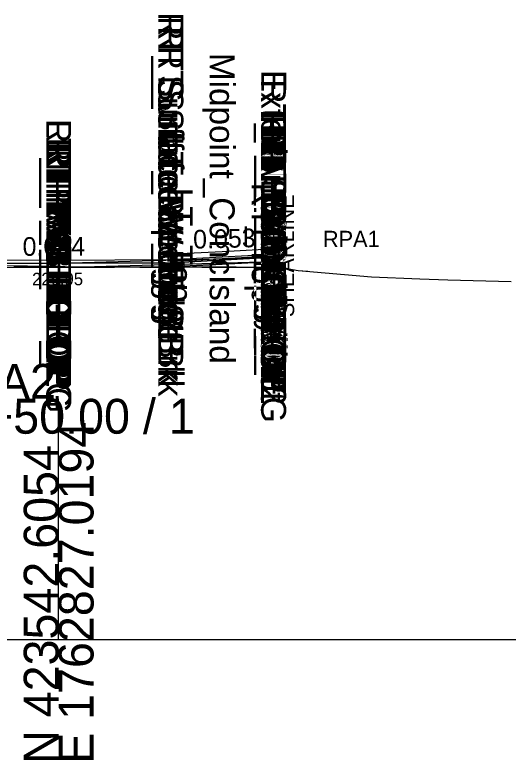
# Model space of a CAD drawing. Extents: x -26 to 3240, y -10 to 12522.
# Drawn here: x 96.5 to 136.1, y 1490.3 to 1550.2 of the extents above; entities that cross this region are included whole.
import ezdxf

# ---------------------------------------------------------------- set-up
doc = ezdxf.new("R2010")
doc.units = 0
for name, color, linetype in [('Exist CMT Pavement', 7, 'Continuous'), ('Exist Cross Section Cell', 7, 'Continuous'), ('Exist XS Center Line Elevation Label', 7, 'Continuous'), ('Exist XS Ground Line', 7, 'Continuous'), ('Prop CMT Concrete Structures', 7, 'Continuous'), ('Prop CMT DNC', 7, 'Continuous'), ('Prop CMT Pvmt Course 1', 7, 'Continuous'), ('Prop CMT Pvmt Course 1 Wedge', 7, 'Continuous'), ('Prop CMT Pvmt Course 2', 7, 'Continuous'), ('Prop CMT Pvmt Course 2 Wedge', 7, 'Continuous'), ('Prop CMT Pvmt Course 3', 7, 'Continuous'), ('Prop CMT Pvmt Course 3 Wedge', 7, 'Continuous'), ('Prop CMT Pvmt Surface', 7, 'Continuous'), ('Prop CMT Pvmt Wedge Surface 1', 7, 'Continuous'), ('Prop CMT Pvmt Wedge Surface 2', 7, 'Continuous'), ('Prop CMT Pvmt Wedge Surface 3', 7, 'Continuous'), ('Prop CMT Shear Line', 7, 'Continuous'), ('Prop CMT Shear Line Text', 7, 'Continuous'), ('Prop CMT Subgrade Earthwork', 7, 'Continuous'), ('Prop XS SE Text', 7, 'Continuous'), ('Scratch_Level_0', 7, 'Continuous')]:
    doc.layers.add(name, color=color, linetype=linetype)

msp = doc.modelspace()

# ---------------------------------------------------------------- linework, layer by layer
at = {"layer": 'Exist CMT Pavement'}
for points in [[(100, 1529.946), (90, 1530.058)], [(100, 1529.946), (90, 1530.058)], [(100, 1529.946), (117.248, 1529.875)], [(100, 1529.946), (117.248, 1529.875)]]:
    msp.add_lwpolyline(points, dxfattribs=at)
at = {"layer": 'Exist Cross Section Cell'}
for p, q in [((100, 1500), (100, 1519.323)), ((0, 1500), (100, 1500)), ((100, 1500), (200, 1500))]:
    msp.add_line(p, q, dxfattribs=at)
at = {"layer": 'Exist XS Ground Line'}
for points in [[(96.393, 1529.982), (96.557, 1529.98), (98.234, 1529.964), (99.198, 1529.955), (100.154, 1529.944), (100.52, 1529.941), (101.642, 1529.925), (102.088, 1529.921), (102.841, 1529.919), (104.97, 1529.914), (106.504, 1529.907), (107.848, 1529.902), (109.73, 1529.911), (110.741, 1529.917), (111.464, 1529.918), (113.742, 1529.916), (114.254, 1529.914), (116.398, 1529.902), (116.439, 1529.901), (116.494, 1529.901), (117.973, 1529.85), (118.184, 1529.825), (119.216, 1529.643), (125.115, 1529.122), (128.99, 1528.958), (131.239, 1528.886), (136.307, 1528.741)], [(96.393, 1529.982), (96.557, 1529.98), (98.234, 1529.964), (99.198, 1529.955), (100.154, 1529.944), (100.52, 1529.941), (101.642, 1529.925), (102.088, 1529.921), (102.841, 1529.919), (104.97, 1529.914), (106.504, 1529.907), (107.848, 1529.902), (109.73, 1529.911), (110.741, 1529.917), (111.464, 1529.918), (113.742, 1529.916), (114.254, 1529.914), (116.398, 1529.902), (116.439, 1529.901), (116.494, 1529.901), (117.973, 1529.85), (118.184, 1529.825), (119.216, 1529.643), (125.115, 1529.122), (128.99, 1528.958), (131.239, 1528.886), (136.306, 1528.741)], [(96.393, 1529.982), (96.557, 1529.98), (98.234, 1529.964), (99.198, 1529.955), (100.154, 1529.944), (100.52, 1529.941), (101.642, 1529.925), (102.088, 1529.921), (102.841, 1529.919), (104.97, 1529.914), (106.504, 1529.907), (107.848, 1529.902), (109.73, 1529.911), (110.741, 1529.917), (111.464, 1529.918), (113.742, 1529.916), (114.254, 1529.914), (116.398, 1529.902), (116.439, 1529.901), (116.494, 1529.901), (117.973, 1529.85), (118.184, 1529.825), (119.216, 1529.643), (120, 1529.574)]]:
    msp.add_lwpolyline(points, dxfattribs=at)
at = {"layer": 'Prop CMT Concrete Structures'}
for points in [[(117.248, 1531.11), (116.498, 1531.32), (113.124, 1531.14), (109.75, 1530.96), (109, 1530.67)], [(117.248, 1531.11), (116.498, 1531.32), (113.124, 1531.14), (109.75, 1530.96), (109, 1530.67)], [(117.248, 1530.818), (117.248, 1531.11)], [(117.248, 1530.818), (117.248, 1531.11)], [(109, 1530.377), (117.248, 1530.818)], [(109, 1530.377), (117.248, 1530.818)], [(109, 1530.67), (109, 1530.377)], [(109, 1530.67), (109, 1530.377)]]:
    msp.add_lwpolyline(points, dxfattribs=at)
at = {"layer": 'Prop CMT DNC'}
msp.add_lwpolyline([(117.248, 1529.777), (117.248, 1531.277)], dxfattribs=at)
msp.add_lwpolyline([(117.248, 1529.777), (117.248, 1531.277)], dxfattribs=at)
at = {"layer": 'Prop CMT Pvmt Course 1'}
for points in [[(100, 1530.463), (79.22, 1530.371)], [(100, 1530.463), (109, 1530.503), (117.248, 1530.943)], [(100, 1530.463), (109, 1530.503), (117.248, 1530.943)], [(117.248, 1530.693), (109, 1530.253), (100, 1530.213)], [(117.248, 1530.693), (109, 1530.253), (100, 1530.213)], [(100, 1530.213), (100, 1530.463)], [(100, 1530.213), (100, 1530.463)], [(100, 1530.213), (100, 1530.463)], [(117.248, 1530.943), (117.248, 1530.693), (117.248, 1530.693), (117.248, 1530.693)], [(117.248, 1530.943), (117.248, 1530.693), (117.248, 1530.693), (117.248, 1530.693)], [(90, 1530.169), (100, 1530.213)], [(100, 1530.213), (100, 1530.213), (100, 1530.213)], [(100, 1530.213), (100, 1530.213), (100, 1530.213)], [(100, 1530.213), (100, 1530.213), (100, 1530.213)]]:
    msp.add_lwpolyline(points, dxfattribs=at)
at = {"layer": 'Prop CMT Pvmt Course 1 Wedge'}
for points in [[(100, 1530.213), (117.248, 1530.693)], [(100, 1530.213), (117.248, 1530.693)], [(117.248, 1530.693), (109, 1530.253)], [(117.248, 1530.693), (109, 1530.253)], [(100, 1530.213), (90, 1530.169)], [(100, 1530.213), (90, 1530.169)], [(109, 1530.253), (100, 1530.213)], [(109, 1530.253), (100, 1530.213)]]:
    msp.add_lwpolyline(points, dxfattribs=at)
at = {"layer": 'Prop CMT Pvmt Course 2'}
for points in [[(117.248, 1530.36), (117.248, 1530.36), (117.248, 1530.693), (117.248, 1530.693)], [(117.248, 1530.693), (117.248, 1530.36)], [(117.248, 1530.36), (117.248, 1530.36), (117.248, 1530.693), (117.248, 1530.693)], [(117.248, 1530.693), (117.248, 1530.36)]]:
    msp.add_lwpolyline(points, dxfattribs=at)
at = {"layer": 'Prop CMT Pvmt Course 2 Wedge'}
for points in [[(100, 1530.213), (117.248, 1530.693)], [(100, 1530.213), (117.248, 1530.693)], [(117.248, 1530.693), (109, 1530.253)], [(117.248, 1530.693), (109, 1530.253)], [(100, 1530.213), (90, 1530.169)], [(100, 1530.213), (90, 1530.169)], [(109, 1530.253), (100, 1530.213)], [(109, 1530.253), (100, 1530.213)]]:
    msp.add_lwpolyline(points, dxfattribs=at)
at = {"layer": 'Prop CMT Pvmt Course 3'}
for points in [[(117.248, 1530.36), (117.248, 1530.36), (117.248, 1529.777), (117.248, 1529.777)], [(117.248, 1529.777), (117.248, 1530.36)], [(117.248, 1530.36), (117.248, 1530.36), (117.248, 1529.777), (117.248, 1529.777)], [(117.248, 1529.777), (117.248, 1530.36)]]:
    msp.add_lwpolyline(points, dxfattribs=at)
at = {"layer": 'Prop CMT Pvmt Course 3 Wedge'}
for points in [[(100, 1529.88), (90, 1529.836)], [(100, 1529.88), (90, 1529.836)], [(100, 1529.88), (117.248, 1530.36)], [(100, 1529.88), (117.248, 1530.36)], [(109, 1529.919), (100, 1529.88)], [(109, 1529.919), (100, 1529.88)], [(117.248, 1530.36), (109, 1529.919)], [(117.248, 1530.36), (109, 1529.919)]]:
    msp.add_lwpolyline(points, dxfattribs=at)
at = {"layer": 'Prop CMT Pvmt Surface'}
for points in [[(100, 1530.463), (79.22, 1530.371)], [(100, 1530.463), (109, 1530.503), (117.248, 1530.943)], [(100, 1530.463), (109, 1530.503), (117.248, 1530.943)]]:
    msp.add_lwpolyline(points, dxfattribs=at)
at = {"layer": 'Prop CMT Pvmt Wedge Surface 1'}
for points in [[(100, 1530.213), (109, 1530.253), (117.248, 1530.693)], [(100, 1530.213), (109, 1530.253), (117.248, 1530.693)], [(117.248, 1530.693), (117.248, 1530.943)], [(117.248, 1530.693), (117.248, 1530.943)], [(117.248, 1530.693), (117.248, 1530.693), (117.248, 1530.693)], [(117.248, 1530.693), (117.248, 1530.693), (117.248, 1530.693)], [(100, 1530.213), (90, 1530.169)]]:
    msp.add_lwpolyline(points, dxfattribs=at)
at = {"layer": 'Prop CMT Pvmt Wedge Surface 2'}
for points in [[(100, 1530.213), (109, 1530.253), (117.248, 1530.693)], [(100, 1530.213), (109, 1530.253), (117.248, 1530.693)], [(117.248, 1530.693), (117.248, 1530.943)], [(117.248, 1530.693), (117.248, 1530.943)], [(100, 1530.213), (79.22, 1530.121)]]:
    msp.add_lwpolyline(points, dxfattribs=at)
at = {"layer": 'Prop CMT Pvmt Wedge Surface 3'}
for points in [[(117.248, 1530.36), (117.248, 1530.943)], [(117.248, 1530.36), (117.248, 1530.943)], [(100, 1529.88), (79.22, 1529.788)], [(100, 1529.88), (109, 1529.919), (117.248, 1530.36)], [(100, 1529.88), (109, 1529.919), (117.248, 1530.36)]]:
    msp.add_lwpolyline(points, dxfattribs=at)
at = {"layer": 'Prop CMT Shear Line'}
for points in [[(117.248, 1535.047), (117.248, 1525.047)], [(117.248, 1534.777), (117.248, 1524.777)], [(117.248, 1534.777), (117.248, 1524.777)]]:
    msp.add_lwpolyline(points, dxfattribs=at)
at = {"layer": 'Prop CMT Subgrade Earthwork'}
for points in [[(117.248, 1529.777), (117.233, 1529.876)], [(117.248, 1529.777), (117.233, 1529.876)], [(117.248, 1529.777), (117.258, 1529.875)], [(117.248, 1529.777), (117.258, 1529.875)], [(117.248, 1529.777), (117.248, 1529.777)], [(117.248, 1529.777), (117.248, 1529.777)]]:
    msp.add_lwpolyline(points, dxfattribs=at)

# ---------------------------------------------------------------- texts
at = {"layer": 'Exist Cross Section Cell'}
for s, p in [('RPA2', (90, 1519.323)), ('11+50.00 / 1', (90, 1516.523))]:
    msp.add_text(s, height=2.8, dxfattribs=at).set_placement(p)
for s, p in [('E 1762827.0194', (102.8, 1490)), ('N 423542.6054', (100, 1490))]:
    msp.add_text(s, height=2.8, rotation=90, dxfattribs=at).set_placement(p)
at = {"layer": 'Exist XS Center Line Elevation Label'}
msp.add_text('226.95', height=1, dxfattribs=at).set_placement((97.87, 1528.446))
at = {"layer": 'Prop CMT Shear Line Text'}
for s, rotation, p in [('SHEARLINE', 90, (118.898, 1525.884)), ('RPA1', 360, (121.211, 1531.517))]:
    msp.add_text(s, height=1.3, rotation=rotation, dxfattribs=at).set_placement(p)
at = {"layer": 'Prop XS SE Text'}
for s, rotation, p in [('0.053', 1.50722, (110.808, 1531.379)), ('0.004', 0.25248, (97.109, 1530.807))]:
    msp.add_text(s, height=1.5, rotation=rotation, dxfattribs=at).set_placement(p)
at = {"layer": 'Scratch_Level_0'}
for s, height, rotation, p in [('RT_Surface Wedge2 Brk', 2, 270, (108, 1550.379)), ('RT_Surface Wedge3 Brk', 2, 270, (108, 1550.045)), ('RT_Surface Wedge1 Brk', 2, 270, (108, 1549.245)), ('RT_Surfacce Brk Pt', 2, 270, (108, 1547.684)), ('Midpoint_ConcIsland', 2, 270, (112.124, 1547.109)), ('Exterior Boundary', 2, 270, (116.258, 1545.733)), ('RT_PV_Sub_Tie_Out', 2, 270, (116.233, 1544.978)), ('RT_PV_OEEOP_EG', 2, 270, (116.248, 1542.379)), ('RT_SL_Pt1', 2, 270, (116.248, 1542.1)), ('RT_PV_IEEOP_EG', 2, 270, (99, 1541.804)), ('LT_PV_IEEOP_EG', 2, 270, (99, 1541.757)), ('RT_PV2_OEEOP', 2, 270, (116.248, 1541.433)), ('RT_Top_Edge', 2, 270, (116.248, 1541.189)), ('RT_Bot_Edge', 2, 270, (116.248, 1540.865)), ('RT_PV3_OEEOP', 2, 270, (116.248, 1541.1)), ('RT_PV1_OEEOP', 2, 270, (116.248, 1540.867)), ('RT_PV2_IEEOP', 2, 270, (99, 1540.307)), ('LT_PV2_IEEOP', 2, 270, (99, 1540.26)), ('LT_Top_Edge', 2, 270, (108, 1540.701)), ('LT_Bot_Edge', 2, 270, (108, 1540.377)), ('RT_Sub_OEEOP', 2, 270, (116.248, 1540.611)), ('RT_PV2_OEOT', 2, 270, (116.248, 1540.567)), ('RT_SL_Label', 2, 270, (116.248, 1540.552)), ('RT_PV1_OEOT', 2, 270, (116.248, 1540.25)), ('RT_PV3_OEOT', 2, 270, (116.248, 1540.234)), ('RT_PV3_IEEOP', 2, 270, (99, 1539.974)), ('LT_PV3_IEEOP', 2, 270, (99, 1539.927)), ('RT_PV1_IEEOP', 2, 270, (99, 1539.741)), ('LT_PV1_IEEOP', 2, 270, (99, 1539.693)), ('RT_Sub_OEOT', 2, 270, (116.248, 1539.745)), ('RT_Slope_Fill', 2, 270, (116.258, 1539.402)), ('RT_Top', 2, 270, (115.498, 1536.691)), ('PV2_PGL', 2, 270, (99, 1536.307)), ('LT_Top', 2, 270, (108.75, 1536.283)), ('PV1_PGL', 2, 270, (99, 1535.991)), ('RT_SL_Pt1', 0.02, 180, (117.321, 1534.787)), ('RT_SL_Pt2', 2, 270, (116.248, 1532.666)), ('Midpoint_ConcIsland', 0.02, 180, (113.284, 1531.15)), ('RT_Top', 0.02, 180, (116.552, 1531.33)), ('RT_Top_Edge', 0.02, 180, (117.349, 1531.12)), ('RT_SL_Label', 0.02, 180, (117.341, 1531.287)), ('PV1_PGL', 0.02, 180, (100.055, 1530.473)), ('LT_Top_Edge', 0.02, 180, (109.1, 1530.68)), ('RT_Surfacce Brk Pt', 0.02, 180, (109.172, 1530.513)), ('LT_Top', 0.02, 180, (109.803, 1530.97)), ('RT_PV1_OEEOP', 0.02, 180, (117.35, 1530.703)), ('RT_PV2_OEEOP', 0.02, 180, (117.356, 1530.703)), ('RT_PV1_OEOT', 0.02, 180, (117.341, 1530.953)), ('RT_PV2_OEOT', 0.02, 180, (117.347, 1530.703)), ('RT_Bot_Edge', 0.02, 180, (117.349, 1530.828)), ('RT_PV_IEEOP_EG', 0.02, 180, (100.119, 1529.956)), ('LT_PV_IEEOP_EG', 0.02, 180, (100.118, 1529.956)), ('RT_PV1_IEEOP', 0.02, 180, (100.095, 1530.223)), ('LT_PV1_IEEOP', 0.02, 180, (100.095, 1530.223)), ('RT_PV2_IEEOP', 0.02, 180, (100.101, 1530.223)), ('RT_PV3_IEEOP', 0.02, 180, (100.101, 1529.89)), ('LT_PV2_IEEOP', 0.02, 180, (100.1, 1530.223)), ('LT_PV3_IEEOP', 0.02, 180, (100.1, 1529.89)), ('PV2_PGL', 0.02, 180, (100.061, 1530.223)), ('RT_Surface Wedge1 Brk', 0.02, 180, (109.19, 1530.263)), ('RT_Surface Wedge2 Brk', 0.02, 180, (109.201, 1530.263)), ('RT_Surface Wedge3 Brk', 0.02, 180, (109.201, 1529.929)), ('LT_Bot_Edge', 0.02, 180, (109.1, 1530.387)), ('RT_PV_Sub_Tie_Out', 0.02, 180, (117.384, 1529.886)), ('RT_PV_OEEOP_EG', 0.02, 180, (117.373, 1529.885)), ('RT_PV3_OEEOP', 0.02, 180, (117.356, 1530.37)), ('RT_PV3_OEOT', 0.02, 180, (117.347, 1530.37)), ('RT_Slope_Fill', 0.02, 180, (117.353, 1529.885)), ('Exterior Boundary', 0.02, 180, (117.417, 1529.885)), ('RT_Sub_OEEOP', 0.02, 180, (117.357, 1529.787)), ('RT_Sub_OEOT', 0.02, 180, (117.348, 1529.787)), ('RT_SL_Pt2', 0.02, 180, (117.327, 1524.787))]:
    msp.add_text(s, height=height, rotation=rotation, dxfattribs=at).set_placement(p)

doc.saveas('drawing.dxf')
